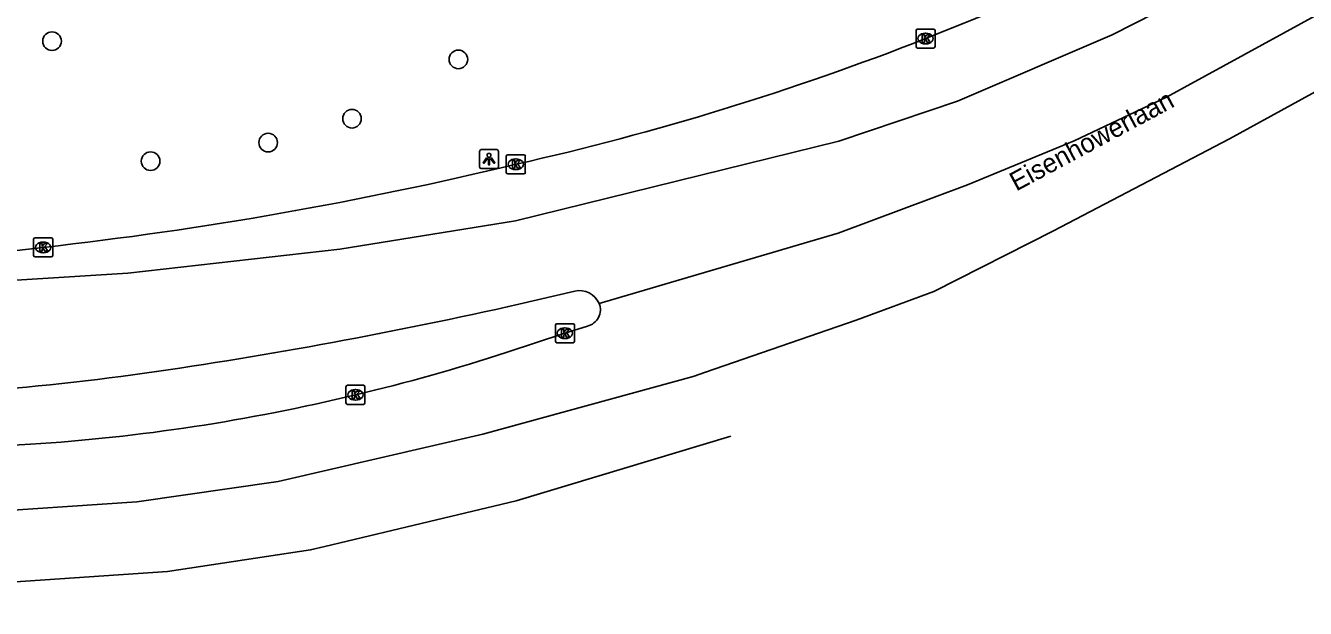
# Model space of a CAD drawing. Extents: x 162417 to 163721, y 384268 to 385416.
# Drawn here: x 162911.4 to 162978.6, y 384270 to 384300.7 of the extents above; entities that cross this region are included whole.
import ezdxf

# ---------------------------------------------------------------- set-up
doc = ezdxf.new("R2010")
doc.units = 0
for name, color, linetype in [('IMGEO_Boom', 7, 'Continuous'), ('IMGEO_Kolk', 7, 'Continuous'), ('IMGEO_Lichtpunt', 7, 'Continuous'), ('IMGEO_Openbare_ruimte_label', 7, 'Continuous'), ('IMGEO_Rijbaan_regionaal_gesloten', 7, 'Continuous')]:
    doc.layers.add(name, color=color, linetype=linetype)

msp = doc.modelspace()

# ---------------------------------------------------------------- linework, layer by layer
at = {"layer": 'IMGEO_Boom'}
for centre in [(162912.748, 384299.847), (162934.088, 384298.886), (162928.502, 384295.77), (162924.098, 384294.515), (162917.924, 384293.54)]:
    msp.add_circle(centre, 0.489, dxfattribs=at)
at = {"layer": 'IMGEO_Kolk'}
for p, q in [((162958.121, 384299.557), (162958.121, 384300.409)), ((162958.196, 384300.483), (162959.048, 384300.483)), ((162958.609, 384300.263), (162958.634, 384300.263)), ((162959.122, 384300.409), (162959.122, 384299.557)), ((162959.048, 384299.483), (162958.196, 384299.483)), ((162958.632, 384299.703), (162958.607, 384299.703)), ((162936.603, 384292.949), (162936.603, 384293.801)), ((162936.678, 384293.875), (162937.53, 384293.875)), ((162937.091, 384293.655), (162937.116, 384293.655)), ((162937.604, 384293.801), (162937.604, 384292.949)), ((162937.53, 384292.875), (162936.678, 384292.875)), ((162937.114, 384293.095), (162937.089, 384293.095)), ((162911.781, 384288.581), (162911.781, 384289.433)), ((162911.856, 384289.507), (162912.708, 384289.507)), ((162912.782, 384289.433), (162912.782, 384288.581)), ((162912.292, 384288.727), (162912.267, 384288.727)), ((162912.269, 384289.287), (162912.294, 384289.287)), ((162912.708, 384288.507), (162911.856, 384288.507)), ((162939.181, 384284.07), (162939.181, 384284.922)), ((162939.256, 384284.996), (162940.108, 384284.996)), ((162939.669, 384284.776), (162939.694, 384284.776)), ((162940.182, 384284.922), (162940.182, 384284.07)), ((162940.108, 384283.996), (162939.256, 384283.996)), ((162939.692, 384284.216), (162939.667, 384284.216)), ((162928.182, 384280.831), (162928.182, 384281.683)), ((162928.257, 384281.757), (162929.109, 384281.757)), ((162928.67, 384281.537), (162928.695, 384281.537)), ((162929.183, 384281.683), (162929.183, 384280.831)), ((162929.109, 384280.757), (162928.257, 384280.757)), ((162928.693, 384280.977), (162928.668, 384280.977))]:
    msp.add_line(p, q, dxfattribs=at)
for points in [[(162958.121, 384299.557), (162958.121, 384300.409)], [(162958.196, 384300.483), (162959.048, 384300.483)], [(162958.442, 384300.183), (162958.565, 384300.183), (162958.565, 384300.032), (162958.695, 384300.183), (162958.859, 384300.183), (162958.713, 384300.032), (162958.866, 384299.783), (162958.714, 384299.783), (162958.629, 384299.947), (162958.565, 384299.88), (162958.565, 384299.783), (162958.442, 384299.783), (162958.442, 384300.183)], [(162959.122, 384300.409), (162959.122, 384299.557)], [(162959.048, 384299.483), (162958.196, 384299.483)], [(162936.603, 384292.949), (162936.603, 384293.801)], [(162936.678, 384293.875), (162937.53, 384293.875)], [(162936.924, 384293.575), (162937.047, 384293.575), (162937.047, 384293.424), (162937.177, 384293.575), (162937.341, 384293.575), (162937.195, 384293.424), (162937.348, 384293.175), (162937.196, 384293.175), (162937.111, 384293.339), (162937.047, 384293.272), (162937.047, 384293.175), (162936.924, 384293.175), (162936.924, 384293.575)], [(162937.604, 384293.801), (162937.604, 384292.949)], [(162937.53, 384292.875), (162936.678, 384292.875)], [(162911.781, 384288.581), (162911.781, 384289.433)], [(162911.856, 384289.507), (162912.708, 384289.507)], [(162912.782, 384289.433), (162912.782, 384288.581)], [(162912.102, 384289.207), (162912.225, 384289.207), (162912.225, 384289.056), (162912.355, 384289.207), (162912.519, 384289.207), (162912.373, 384289.056), (162912.526, 384288.807), (162912.374, 384288.807), (162912.289, 384288.971), (162912.225, 384288.904), (162912.225, 384288.807), (162912.102, 384288.807), (162912.102, 384289.207)], [(162912.708, 384288.507), (162911.856, 384288.507)], [(162939.181, 384284.07), (162939.181, 384284.922)], [(162939.256, 384284.996), (162940.108, 384284.996)], [(162939.502, 384284.696), (162939.625, 384284.696), (162939.625, 384284.545), (162939.755, 384284.696), (162939.919, 384284.696), (162939.773, 384284.545), (162939.926, 384284.296), (162939.774, 384284.296), (162939.689, 384284.46), (162939.625, 384284.393), (162939.625, 384284.296), (162939.502, 384284.296), (162939.502, 384284.696)], [(162940.182, 384284.922), (162940.182, 384284.07)], [(162940.108, 384283.996), (162939.256, 384283.996)], [(162928.182, 384280.831), (162928.182, 384281.683)], [(162928.257, 384281.757), (162929.109, 384281.757)], [(162928.503, 384281.457), (162928.626, 384281.457), (162928.626, 384281.306), (162928.756, 384281.457), (162928.92, 384281.457), (162928.774, 384281.306), (162928.927, 384281.057), (162928.775, 384281.057), (162928.69, 384281.221), (162928.626, 384281.154), (162928.626, 384281.057), (162928.503, 384281.057), (162928.503, 384281.457)], [(162929.183, 384281.683), (162929.183, 384280.831)], [(162929.109, 384280.757), (162928.257, 384280.757)]]:
    msp.add_lwpolyline(points, dxfattribs=at)
for centre, start, end in [((162958.198, 384300.407), 91.55205, 178.44795), ((162958.198, 384300.407), 91.55205, 178.44795), ((162959.046, 384300.407), 1.55205, 88.44795), ((162959.046, 384300.407), 1.55205, 88.44795), ((162958.198, 384299.559), 181.55205, 268.44795), ((162958.198, 384299.559), 181.55205, 268.44795), ((162959.046, 384299.559), 271.55205, 358.44795), ((162959.046, 384299.559), 271.55205, 358.44795), ((162936.68, 384293.799), 91.55205, 178.44795), ((162936.68, 384293.799), 91.55205, 178.44795), ((162937.528, 384293.799), 1.55205, 88.44795), ((162937.528, 384293.799), 1.55205, 88.44795), ((162936.68, 384292.951), 181.55205, 268.44795), ((162936.68, 384292.951), 181.55205, 268.44795), ((162937.528, 384292.951), 271.55205, 358.44795), ((162937.528, 384292.951), 271.55205, 358.44795), ((162911.858, 384289.431), 91.55205, 178.44795), ((162911.858, 384289.431), 91.55205, 178.44795), ((162912.706, 384289.431), 1.55205, 88.44795), ((162912.706, 384289.431), 1.55205, 88.44795), ((162911.858, 384288.583), 181.55205, 268.44795), ((162911.858, 384288.583), 181.55205, 268.44795), ((162912.706, 384288.583), 271.55205, 358.44795), ((162912.706, 384288.583), 271.55205, 358.44795), ((162939.258, 384284.92), 91.55205, 178.44795), ((162939.258, 384284.92), 91.55205, 178.44795), ((162940.106, 384284.92), 1.55205, 88.44795), ((162940.106, 384284.92), 1.55205, 88.44795), ((162939.258, 384284.072), 181.55205, 268.44795), ((162939.258, 384284.072), 181.55205, 268.44795), ((162940.106, 384284.072), 271.55205, 358.44795), ((162940.106, 384284.072), 271.55205, 358.44795), ((162928.259, 384281.681), 91.55205, 178.44795), ((162928.259, 384281.681), 91.55205, 178.44795), ((162929.107, 384281.681), 1.55205, 88.44795), ((162929.107, 384281.681), 1.55205, 88.44795), ((162928.259, 384280.833), 181.55205, 268.44795), ((162928.259, 384280.833), 181.55205, 268.44795), ((162929.107, 384280.833), 271.55205, 358.44795), ((162929.107, 384280.833), 271.55205, 358.44795)]:
    msp.add_arc(centre, 0.0765, start, end, dxfattribs=at)
for centre, major_axis, ratio, start_param, end_param in [((162958.608, 384299.983), (-0.387, 0.002), 0.722429, 4.712389, 7.853982), ((162958.633, 384299.983), (-0.39, 0.002), 0.717154, 1.570796, 4.712389), ((162937.09, 384293.375), (-0.387, 0.002), 0.722429, 4.712389, 7.853982), ((162937.115, 384293.375), (-0.39, 0.002), 0.717154, 1.570796, 4.712389), ((162912.268, 384289.007), (-0.387, 0.002), 0.722429, 4.712389, 7.853982), ((162912.293, 384289.007), (-0.39, 0.002), 0.717154, 1.570796, 4.712389), ((162939.668, 384284.496), (-0.387, 0.002), 0.722429, 4.712389, 7.853982), ((162939.693, 384284.496), (-0.39, 0.002), 0.717154, 1.570796, 4.712389), ((162928.669, 384281.257), (-0.387, 0.002), 0.722429, 4.712389, 7.853982), ((162928.694, 384281.257), (-0.39, 0.002), 0.717154, 1.570796, 4.712389)]:
    msp.add_ellipse(centre, major_axis=major_axis, ratio=ratio, start_param=start_param, end_param=end_param, dxfattribs=at)
at = {"layer": 'IMGEO_Lichtpunt'}
for p, q in [((162936.099, 384294.145), (162935.291, 384294.145)), ((162936.099, 384294.145), (162935.291, 384294.145)), ((162935.197, 384294.05), (162935.197, 384293.243)), ((162935.197, 384294.05), (162935.197, 384293.243)), ((162936.193, 384293.243), (162936.193, 384294.05)), ((162936.193, 384293.243), (162936.193, 384294.05)), ((162935.291, 384293.149), (162936.099, 384293.149)), ((162935.291, 384293.149), (162936.099, 384293.149))]:
    msp.add_line(p, q, dxfattribs=at)
for points in [[(162935.571, 384293.714), (162935.61, 384293.686), (162935.422, 384293.424), (162935.384, 384293.451), (162935.571, 384293.714)], [(162935.673, 384293.666), (162935.72, 384293.666), (162935.72, 384293.344), (162935.673, 384293.344), (162935.673, 384293.666)], [(162935.783, 384293.686), (162935.821, 384293.713), (162936.008, 384293.451), (162935.969, 384293.423), (162935.783, 384293.686)]]:
    msp.add_lwpolyline(points, dxfattribs=at)
msp.add_circle((162935.696, 384293.848), 0.0994, dxfattribs=at)
for centre, start, end in [((162935.291, 384294.05), 90, 180), ((162935.291, 384294.05), 90, 180), ((162936.099, 384294.05), 0, 90), ((162936.099, 384294.05), 0, 90), ((162935.291, 384293.243), 180, 270), ((162935.291, 384293.243), 180, 270), ((162936.099, 384293.243), 270, 0), ((162936.099, 384293.243), 270, 360)]:
    msp.add_arc(centre, 0.0946, start, end, dxfattribs=at)
at = {"layer": 'IMGEO_Rijbaan_regionaal_gesloten'}
for points in [[(162941.479, 384286.061), (162954.028, 384289.762), (162960.828, 384292.291), (162966.432, 384294.615), (162971.284, 384296.905), (163023.955, 384325.752), (163039.503, 384334.559), (163060.953, 384346.598), (163087.014, 384362.042), (163116.021, 384379.055), (163121.264, 384382.351)], [(163123.086, 384378.886), (163121.238, 384377.799), (163114.166, 384373.602), (163083.13, 384355.508), (163054.517, 384339.003), (163012.884, 384315.76), (162974.583, 384294.713), (162965.348, 384289.868), (162959.065, 384286.688), (162954.978, 384285.174), (162947.06, 384282.44), (162946.424, 384282.221), (162935.372, 384279.193), (162924.623, 384276.694), (162917.205, 384275.634), (162908.348, 384275.029), (162883.151, 384273.384)], [(163095.345, 384370.155), (163062.567, 384351.646), (163043.94, 384341.207), (163012.701, 384323.519), (162984.217, 384308.223), (162968.416, 384300.177), (162960.299, 384296.697), (162954.066, 384294.595), (162937.096, 384290.408), (162927.858, 384288.907), (162916.73, 384287.644), (162906.103, 384286.986), (162895.79, 384287.17), (162884.742, 384288.671), (162884.016, 384289.125)], [(162937.266, 384286.016), (162940.195, 384286.71)], [(162940.867, 384284.87), (162939.682, 384284.494), (162936.646, 384283.494)], [(162911.617, 384278.658), (162905.39, 384278.294), (162887.921, 384277.251), (162880.557, 384276.791)], [(162885.705, 384270.031), (162885.857, 384270.04), (162909.803, 384271.365), (162918.815, 384271.976), (162926.325, 384273.103), (162927.076, 384273.283), (162931.764, 384274.404), (162937.121, 384275.685), (162948.399, 384279.09)]]:
    msp.add_lwpolyline(points, dxfattribs=at)
for centre, radius, start, end in [((162877.734, 384505.39), 220.762, 291.49467, 297.35289), ((162904.713, 384437.185), 147.415, 282.6931, 291.45135), ((162889.947, 384488.685), 200.924, 276.38224, 283.57393), ((162897.906, 384401.341), 113.251, 273.52382, 277.29266), ((162940.446, 384285.611), 1.127, 23.52859, 102.84262), ((162881.183, 384534.877), 255.102, 278.20963, 282.70004), ((162940.663, 384285.728), 0.882, 283.40658, 22.20033), ((162905.852, 384377.778), 99.185, 283.30824, 288.08778), ((162894.73, 384450.545), 169.705, 270.99235, 277.74837), ((162905.197, 384378.18), 99.728, 273.69077, 283.62087)]:
    msp.add_arc(centre, radius, start, end, dxfattribs=at)

# ---------------------------------------------------------------- texts
at = {"layer": 'IMGEO_Openbare_ruimte_label'}
msp.add_text('Eisenhowerlaan', height=1, rotation=28.2309, dxfattribs=at).set_placement((162963.384, 384291.937))

doc.saveas('drawing.dxf')
